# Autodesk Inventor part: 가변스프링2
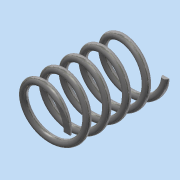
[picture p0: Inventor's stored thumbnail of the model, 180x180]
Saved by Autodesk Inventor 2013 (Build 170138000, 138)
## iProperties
Created: 2018-10
Part Number: 가변스프링2
Material: 스테인리스강
Document SubType Name: Modeling
Designer: Administrator
Density: 8.08 g/cm^3
Mass: 6.29306 g
Surface Area: 15.7947 cm^2
Volume: 0.778844 cm^3
Author: Administrator
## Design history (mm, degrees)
sketch "스케치1"
  geometry: L1 (0, 0)-(8, 0); L2 (0, 0)-(0, 29.849); L3 (0, 29.849)-(8, 29.849); C1 r 1 at (8, 0)
  constraints: 6 end point, 2 perpendicular, 1 centre point, 1 coincident, 1 horizontal
  dimensions: "d0" = 8 distance of L1.start L1.end; "d1" = 29.84941 distance of L1.start L2.end (derived); "d2" = 8 distance of L2.end L3.end; "d3" = 2 diameter of C1
feature "코일1" sketch "스케치1" pitch "d4" = 10; turns "d6" = 5; dims "d5" = 29.84941 (= d1), "d7" = 0, angle "d8" = 90 deg, angle "d9" = 90 deg, "d10" = 0, "d11" = 0
sketch "스케치2"
  geometry: L1 (29.849, 10)-(0, 10); L2 (0, 10)-(0, -10); L3 (0, -10)-(29.849, -10); L4 (29.849, -10)-(29.849, 10); 2 further points
  constraints: 8 end point, 2 parallel, 1 coincident, 1 horizontal, 1 midpoint, 1 perpendicular
  dimensions: "d12" = 29.84941 distance of L1.start L1.end (derived); "d14" = 20 distance of L3.end L1.start
extrude "돌출1" sketch "스케치2" stored distance "d15" = 0; taper "d16" = 0 deg
node "솔리드1"
